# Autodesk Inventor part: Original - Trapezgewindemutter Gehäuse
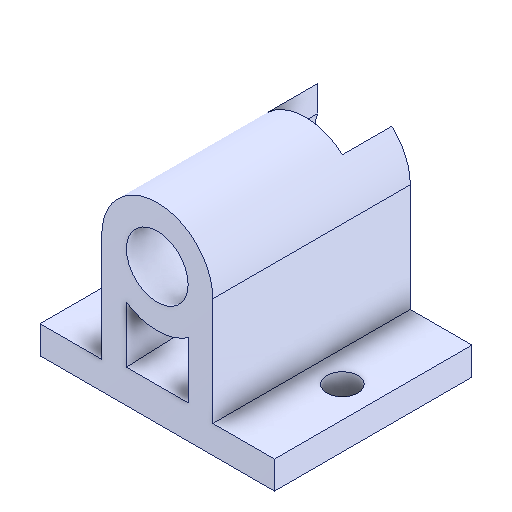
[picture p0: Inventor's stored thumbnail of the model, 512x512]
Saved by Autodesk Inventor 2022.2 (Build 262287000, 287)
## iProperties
Created: 2024-09
Part Number: Original - Trapezgewindemutter Gehäuse
Material: Generico
Document SubType Name: Modeling
Designer: 18907419
Density: 1 g/cm^3
Appearance: Default
Author: 18907419
Revision Number: ANY
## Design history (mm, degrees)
feature "Schnitt-Linear austragen5"
node "Solido1"
